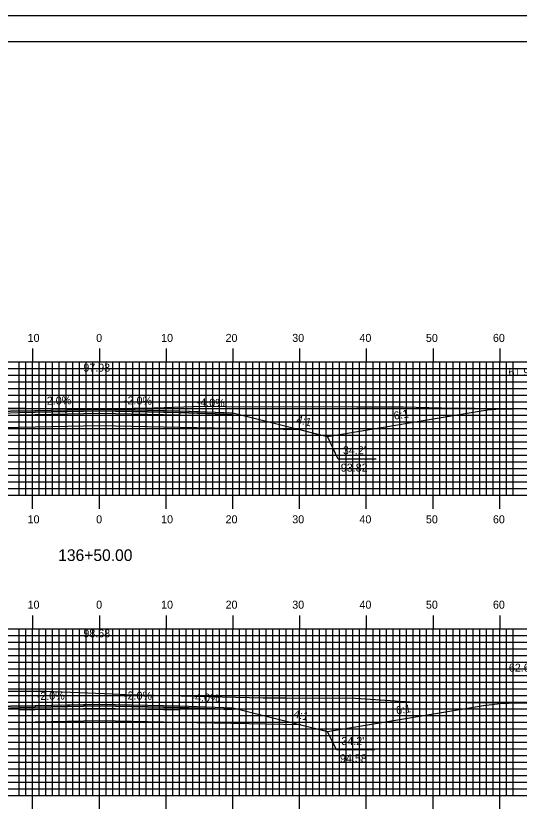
# Model space of a CAD drawing. Extents: x 1775170 to 1775514, y 442591 to 442811.
# Drawn here: x 1775323.7 to 1775399.1, y 442691.2 to 442810.5 of the extents above; entities that cross this region are included whole.
import ezdxf

# ---------------------------------------------------------------- set-up
doc = ezdxf.new("R2010")
doc.units = 0
for name, color, linetype in [('ANNOTATION', 7, 'Continuous'), ('BORDER', 7, 'Continuous'), ('D_Roadway_Centerline', 7, 'Continuous'), ('D_Roadway_Centerline_Text', 7, 'Continuous'), ('D_Roadway_Edge_Shoulder', 7, 'Continuous'), ('D_Roadway_Edge_TW', 7, 'Continuous'), ('D_Roadway_Pavement', 7, 'Continuous'), ('D_Roadway_SlopeLines', 7, 'Continuous'), ('D_Roadway_SubGrade', 7, 'Continuous'), ('D_Text_Standard', 7, 'Continuous'), ('H_V ANNOTATION', 7, 'Continuous'), ('MAJOR', 7, 'Continuous'), ('MINOR', 7, 'Continuous'), ('PLOT BOUNDARY', 7, 'Continuous'), ('S_Roadway_Centerline', 7, 'Continuous')]:
    doc.layers.add(name, color=color, linetype=linetype)

msp = doc.modelspace()

# ---------------------------------------------------------------- linework, layer by layer
at = {"layer": 'ANNOTATION'}
for points in [[(1775377.65, 442744.09), (1775371.96, 442744.09), (1775370.37, 442747.49)], [(1775377.42, 442700.49), (1775371.73, 442700.49), (1775370.37, 442703.24)]]:
    msp.add_lwpolyline(points, dxfattribs=at)
at = {"layer": 'BORDER'}
msp.add_lwpolyline([(1775186.6, 442596.67), (1775506.6, 442596.67), (1775506.6, 442806.67), (1775186.6, 442806.67)], close=True, dxfattribs=at)
at = {"layer": 'D_Roadway_Centerline'}
for points in [[(1775316.2, 442751.03), (1775324.2, 442751.35), (1775326.46, 442751.4), (1775336.2, 442751.59), (1775344.24, 442751.43), (1775348.2, 442751.35), (1775349.77, 442751.29), (1775356.2, 442751.03), (1775363.58, 442749.19), (1775366.37, 442748.49), (1775368.69, 442747.91), (1775370.37, 442747.49), (1775393.09, 442751.28), (1775394.34, 442751.46), (1775395.59, 442751.58), (1775396.58, 442751.63), (1775396.84, 442751.64), (1775398.09, 442751.65)], [(1775316.2, 442706.78), (1775324.2, 442707.1), (1775334.23, 442707.3), (1775336.2, 442707.34), (1775348.2, 442707.1), (1775352.22, 442706.94), (1775356.2, 442706.78), (1775361.8, 442705.38), (1775366.37, 442704.24), (1775369.62, 442703.43), (1775370.37, 442703.24), (1775393.77, 442707.14), (1775393.82, 442707.15), (1775395.02, 442707.32), (1775395.83, 442707.4), (1775396.27, 442707.45), (1775396.93, 442707.48), (1775397.52, 442707.52), (1775398.77, 442707.53)]]:
    msp.add_lwpolyline(points, dxfattribs=at)
at = {"layer": 'D_Roadway_Edge_Shoulder'}
for points in [[(1775324.2, 442751.35), (1775316.2, 442751.03), (1775316.2, 442750.78), (1775324.2, 442751.1)], [(1775348.2, 442751.35), (1775356.2, 442751.03), (1775356.2, 442750.78), (1775348.2, 442751.1)], [(1775324.2, 442707.1), (1775316.2, 442706.78), (1775316.2, 442706.53), (1775324.2, 442706.85)], [(1775348.2, 442707.1), (1775356.2, 442706.78), (1775356.2, 442706.53), (1775348.2, 442706.85)]]:
    msp.add_lwpolyline(points, close=True, dxfattribs=at)
at = {"layer": 'D_Roadway_Edge_TW'}
for points in [[(1775324.2, 442751.1), (1775324.2, 442751.35), (1775336.2, 442751.59), (1775348.2, 442751.35), (1775348.2, 442751.1), (1775336.2, 442751.34)], [(1775324.2, 442706.85), (1775324.2, 442707.1), (1775336.2, 442707.34), (1775348.2, 442707.1), (1775348.2, 442706.85), (1775336.2, 442707.09)]]:
    msp.add_lwpolyline(points, close=True, dxfattribs=at)
at = {"layer": 'D_Roadway_Pavement'}
for points in [[(1775324.2, 442750.69), (1775324.2, 442751.1), (1775336.2, 442751.34), (1775348.2, 442751.1), (1775348.2, 442750.69), (1775336.2, 442750.93)], [(1775324.2, 442706.44), (1775324.2, 442706.85), (1775336.2, 442707.09), (1775348.2, 442706.85), (1775348.2, 442706.44), (1775336.2, 442706.68)]]:
    msp.add_lwpolyline(points, close=True, dxfattribs=at)
at = {"layer": 'D_Roadway_SlopeLines'}
for points in [[(1775370.37, 442747.49), (1775393.09, 442751.28), (1775394.34, 442751.46), (1775395.59, 442751.58), (1775396.84, 442751.64), (1775398.09, 442751.65)], [(1775356.2, 442751.03), (1775370.37, 442747.49)], [(1775370.37, 442703.24), (1775393.77, 442707.14), (1775395.02, 442707.32), (1775396.27, 442707.45), (1775397.52, 442707.52), (1775398.77, 442707.53)], [(1775356.2, 442706.78), (1775370.37, 442703.24)]]:
    msp.add_lwpolyline(points, dxfattribs=at)
at = {"layer": 'D_Roadway_SubGrade'}
for points in [[(1775324.2, 442748.85), (1775306.02, 442748.49), (1775316.2, 442751.03), (1775316.2, 442750.78), (1775324.2, 442751.1), (1775336.2, 442751.34), (1775348.2, 442751.1), (1775356.2, 442750.78), (1775356.2, 442751.03), (1775366.37, 442748.49), (1775348.2, 442748.85), (1775336.2, 442749.09)], [(1775324.2, 442704.6), (1775306.02, 442704.24), (1775316.2, 442706.78), (1775316.2, 442706.53), (1775324.2, 442706.85), (1775336.2, 442707.09), (1775348.2, 442706.85), (1775356.2, 442706.53), (1775356.2, 442706.78), (1775366.37, 442704.24), (1775348.2, 442704.6), (1775336.2, 442704.84)]]:
    msp.add_lwpolyline(points, close=True, dxfattribs=at)
at = {"layer": 'MAJOR'}
for p, q in [((1775326.2, 442760.67), (1775326.2, 442758.67)), ((1775336.2, 442760.67), (1775336.2, 442758.67)), ((1775346.2, 442760.67), (1775346.2, 442758.67)), ((1775356.2, 442760.67), (1775356.2, 442758.67)), ((1775366.2, 442760.67), (1775366.2, 442758.67)), ((1775376.2, 442760.67), (1775376.2, 442758.67)), ((1775386.2, 442760.67), (1775386.2, 442758.67)), ((1775396.2, 442760.67), (1775396.2, 442758.67)), ((1775196.2, 442758.67), (1775476.2, 442758.67)), ((1775196.2, 442758.67), (1775476.2, 442758.67)), ((1775326.2, 442738.67), (1775326.2, 442758.67)), ((1775336.2, 442738.67), (1775336.2, 442758.67)), ((1775346.2, 442738.67), (1775346.2, 442758.67)), ((1775356.2, 442738.67), (1775356.2, 442758.67)), ((1775366.2, 442738.67), (1775366.2, 442758.67)), ((1775376.2, 442738.67), (1775376.2, 442758.67)), ((1775386.2, 442738.67), (1775386.2, 442758.67)), ((1775396.2, 442738.67), (1775396.2, 442758.67)), ((1775196.2, 442753.67), (1775476.2, 442753.67)), ((1775196.2, 442748.67), (1775476.2, 442748.67)), ((1775196.2, 442743.67), (1775476.2, 442743.67)), ((1775196.2, 442738.67), (1775476.2, 442738.67)), ((1775196.2, 442738.67), (1775476.2, 442738.67)), ((1775326.2, 442736.66), (1775326.2, 442738.67)), ((1775336.2, 442736.66), (1775336.2, 442738.67)), ((1775346.2, 442736.66), (1775346.2, 442738.67)), ((1775356.2, 442736.66), (1775356.2, 442738.67)), ((1775366.2, 442736.66), (1775366.2, 442738.67)), ((1775376.2, 442736.66), (1775376.2, 442738.67)), ((1775386.2, 442736.66), (1775386.2, 442738.67)), ((1775396.2, 442736.66), (1775396.2, 442738.67)), ((1775326.2, 442720.67), (1775326.2, 442718.67)), ((1775336.2, 442720.67), (1775336.2, 442718.67)), ((1775346.2, 442720.67), (1775346.2, 442718.67)), ((1775356.2, 442720.67), (1775356.2, 442718.67)), ((1775366.2, 442720.67), (1775366.2, 442718.67)), ((1775376.2, 442720.67), (1775376.2, 442718.67)), ((1775386.2, 442720.67), (1775386.2, 442718.67)), ((1775396.2, 442720.67), (1775396.2, 442718.67)), ((1775196.2, 442718.67), (1775476.2, 442718.67)), ((1775196.2, 442718.67), (1775476.2, 442718.67)), ((1775326.2, 442693.67), (1775326.2, 442718.67)), ((1775336.2, 442693.67), (1775336.2, 442718.67)), ((1775346.2, 442693.67), (1775346.2, 442718.67)), ((1775356.2, 442693.67), (1775356.2, 442718.67)), ((1775366.2, 442693.67), (1775366.2, 442718.67)), ((1775376.2, 442693.67), (1775376.2, 442718.67)), ((1775386.2, 442693.67), (1775386.2, 442718.67)), ((1775396.2, 442693.67), (1775396.2, 442718.67)), ((1775196.2, 442713.67), (1775476.2, 442713.67)), ((1775196.2, 442708.67), (1775476.2, 442708.67)), ((1775196.2, 442703.67), (1775476.2, 442703.67)), ((1775196.2, 442698.67), (1775476.2, 442698.67)), ((1775196.2, 442693.67), (1775476.2, 442693.67)), ((1775196.2, 442693.67), (1775476.2, 442693.67)), ((1775326.2, 442691.66), (1775326.2, 442693.67)), ((1775336.2, 442691.66), (1775336.2, 442693.67)), ((1775346.2, 442691.66), (1775346.2, 442693.67)), ((1775356.2, 442691.66), (1775356.2, 442693.67)), ((1775366.2, 442691.66), (1775366.2, 442693.67)), ((1775376.2, 442691.66), (1775376.2, 442693.67)), ((1775386.2, 442691.66), (1775386.2, 442693.67)), ((1775396.2, 442691.66), (1775396.2, 442693.67))]:
    msp.add_line(p, q, dxfattribs=at)
at = {"layer": 'MINOR'}
for p, q in [((1775324.2, 442738.67), (1775324.2, 442758.67)), ((1775325.2, 442738.67), (1775325.2, 442758.67)), ((1775327.2, 442738.67), (1775327.2, 442758.67)), ((1775328.2, 442738.67), (1775328.2, 442758.67)), ((1775329.2, 442738.67), (1775329.2, 442758.67)), ((1775330.2, 442738.67), (1775330.2, 442758.67)), ((1775331.2, 442738.67), (1775331.2, 442758.67)), ((1775332.2, 442738.67), (1775332.2, 442758.67)), ((1775333.2, 442738.67), (1775333.2, 442758.67)), ((1775334.2, 442738.67), (1775334.2, 442758.67)), ((1775335.2, 442738.67), (1775335.2, 442758.67)), ((1775337.2, 442738.67), (1775337.2, 442758.67)), ((1775338.2, 442738.67), (1775338.2, 442758.67)), ((1775339.2, 442738.67), (1775339.2, 442758.67)), ((1775340.2, 442738.67), (1775340.2, 442758.67)), ((1775341.2, 442738.67), (1775341.2, 442758.67)), ((1775342.2, 442738.67), (1775342.2, 442758.67)), ((1775343.2, 442738.67), (1775343.2, 442758.67)), ((1775344.2, 442738.67), (1775344.2, 442758.67)), ((1775345.2, 442738.67), (1775345.2, 442758.67)), ((1775347.2, 442738.67), (1775347.2, 442758.67)), ((1775348.2, 442738.67), (1775348.2, 442758.67)), ((1775349.2, 442738.67), (1775349.2, 442758.67)), ((1775350.2, 442738.67), (1775350.2, 442758.67)), ((1775351.2, 442738.67), (1775351.2, 442758.67)), ((1775352.2, 442738.67), (1775352.2, 442758.67)), ((1775353.2, 442738.67), (1775353.2, 442758.67)), ((1775354.2, 442738.67), (1775354.2, 442758.67)), ((1775355.2, 442738.67), (1775355.2, 442758.67)), ((1775357.2, 442738.67), (1775357.2, 442758.67)), ((1775358.2, 442738.67), (1775358.2, 442758.67)), ((1775359.2, 442738.67), (1775359.2, 442758.67)), ((1775360.2, 442738.67), (1775360.2, 442758.67)), ((1775361.2, 442738.67), (1775361.2, 442758.67)), ((1775362.2, 442738.67), (1775362.2, 442758.67)), ((1775363.2, 442738.67), (1775363.2, 442758.67)), ((1775364.2, 442738.67), (1775364.2, 442758.67)), ((1775365.2, 442738.67), (1775365.2, 442758.67)), ((1775367.2, 442738.67), (1775367.2, 442758.67)), ((1775368.2, 442738.67), (1775368.2, 442758.67)), ((1775369.2, 442738.67), (1775369.2, 442758.67)), ((1775370.2, 442738.67), (1775370.2, 442758.67)), ((1775371.2, 442738.67), (1775371.2, 442758.67)), ((1775372.2, 442738.67), (1775372.2, 442758.67)), ((1775373.2, 442738.67), (1775373.2, 442758.67)), ((1775374.2, 442738.67), (1775374.2, 442758.67)), ((1775375.2, 442738.67), (1775375.2, 442758.67)), ((1775377.2, 442738.67), (1775377.2, 442758.67)), ((1775378.2, 442738.67), (1775378.2, 442758.67)), ((1775379.2, 442738.67), (1775379.2, 442758.67)), ((1775380.2, 442738.67), (1775380.2, 442758.67)), ((1775381.2, 442738.67), (1775381.2, 442758.67)), ((1775382.2, 442738.67), (1775382.2, 442758.67)), ((1775383.2, 442738.67), (1775383.2, 442758.67)), ((1775384.2, 442738.67), (1775384.2, 442758.67)), ((1775385.2, 442738.67), (1775385.2, 442758.67)), ((1775387.2, 442738.67), (1775387.2, 442758.67)), ((1775388.2, 442738.67), (1775388.2, 442758.67)), ((1775389.2, 442738.67), (1775389.2, 442758.67)), ((1775390.2, 442738.67), (1775390.2, 442758.67)), ((1775391.2, 442738.67), (1775391.2, 442758.67)), ((1775392.2, 442738.67), (1775392.2, 442758.67)), ((1775393.2, 442738.67), (1775393.2, 442758.67)), ((1775394.2, 442738.67), (1775394.2, 442758.67)), ((1775395.2, 442738.67), (1775395.2, 442758.67)), ((1775397.2, 442738.67), (1775397.2, 442758.67)), ((1775398.2, 442738.67), (1775398.2, 442758.67)), ((1775196.2, 442757.67), (1775476.2, 442757.67)), ((1775196.2, 442756.67), (1775476.2, 442756.67)), ((1775196.2, 442755.67), (1775476.2, 442755.67)), ((1775196.2, 442754.67), (1775476.2, 442754.67)), ((1775196.2, 442752.67), (1775476.2, 442752.67)), ((1775196.2, 442751.67), (1775476.2, 442751.67)), ((1775196.2, 442750.67), (1775476.2, 442750.67)), ((1775196.2, 442749.67), (1775476.2, 442749.67)), ((1775196.2, 442747.67), (1775476.2, 442747.67)), ((1775196.2, 442746.67), (1775476.2, 442746.67)), ((1775196.2, 442745.67), (1775476.2, 442745.67)), ((1775196.2, 442744.67), (1775476.2, 442744.67)), ((1775196.2, 442742.67), (1775476.2, 442742.67)), ((1775196.2, 442741.67), (1775476.2, 442741.67)), ((1775196.2, 442740.67), (1775476.2, 442740.67)), ((1775196.2, 442739.67), (1775476.2, 442739.67)), ((1775324.2, 442693.67), (1775324.2, 442718.67)), ((1775325.2, 442693.67), (1775325.2, 442718.67)), ((1775327.2, 442693.67), (1775327.2, 442718.67)), ((1775328.2, 442693.67), (1775328.2, 442718.67)), ((1775329.2, 442693.67), (1775329.2, 442718.67)), ((1775330.2, 442693.67), (1775330.2, 442718.67)), ((1775331.2, 442693.67), (1775331.2, 442718.67)), ((1775332.2, 442693.67), (1775332.2, 442718.67)), ((1775333.2, 442693.67), (1775333.2, 442718.67)), ((1775334.2, 442693.67), (1775334.2, 442718.67)), ((1775335.2, 442693.67), (1775335.2, 442718.67)), ((1775337.2, 442693.67), (1775337.2, 442718.67)), ((1775338.2, 442693.67), (1775338.2, 442718.67)), ((1775339.2, 442693.67), (1775339.2, 442718.67)), ((1775340.2, 442693.67), (1775340.2, 442718.67)), ((1775341.2, 442693.67), (1775341.2, 442718.67)), ((1775342.2, 442693.67), (1775342.2, 442718.67)), ((1775343.2, 442693.67), (1775343.2, 442718.67)), ((1775344.2, 442693.67), (1775344.2, 442718.67)), ((1775345.2, 442693.67), (1775345.2, 442718.67)), ((1775347.2, 442693.67), (1775347.2, 442718.67)), ((1775348.2, 442693.67), (1775348.2, 442718.67)), ((1775349.2, 442693.67), (1775349.2, 442718.67)), ((1775350.2, 442693.67), (1775350.2, 442718.67)), ((1775351.2, 442693.67), (1775351.2, 442718.67)), ((1775352.2, 442693.67), (1775352.2, 442718.67)), ((1775353.2, 442693.67), (1775353.2, 442718.67)), ((1775354.2, 442693.67), (1775354.2, 442718.67)), ((1775355.2, 442693.67), (1775355.2, 442718.67)), ((1775357.2, 442693.67), (1775357.2, 442718.67)), ((1775358.2, 442693.67), (1775358.2, 442718.67)), ((1775359.2, 442693.67), (1775359.2, 442718.67)), ((1775360.2, 442693.67), (1775360.2, 442718.67)), ((1775361.2, 442693.67), (1775361.2, 442718.67)), ((1775362.2, 442693.67), (1775362.2, 442718.67)), ((1775363.2, 442693.67), (1775363.2, 442718.67)), ((1775364.2, 442693.67), (1775364.2, 442718.67)), ((1775365.2, 442693.67), (1775365.2, 442718.67)), ((1775367.2, 442693.67), (1775367.2, 442718.67)), ((1775368.2, 442693.67), (1775368.2, 442718.67)), ((1775369.2, 442693.67), (1775369.2, 442718.67)), ((1775370.2, 442693.67), (1775370.2, 442718.67)), ((1775371.2, 442693.67), (1775371.2, 442718.67)), ((1775372.2, 442693.67), (1775372.2, 442718.67)), ((1775373.2, 442693.67), (1775373.2, 442718.67)), ((1775374.2, 442693.67), (1775374.2, 442718.67)), ((1775375.2, 442693.67), (1775375.2, 442718.67)), ((1775377.2, 442693.67), (1775377.2, 442718.67)), ((1775378.2, 442693.67), (1775378.2, 442718.67)), ((1775379.2, 442693.67), (1775379.2, 442718.67)), ((1775380.2, 442693.67), (1775380.2, 442718.67)), ((1775381.2, 442693.67), (1775381.2, 442718.67)), ((1775382.2, 442693.67), (1775382.2, 442718.67)), ((1775383.2, 442693.67), (1775383.2, 442718.67)), ((1775384.2, 442693.67), (1775384.2, 442718.67)), ((1775385.2, 442693.67), (1775385.2, 442718.67)), ((1775387.2, 442693.67), (1775387.2, 442718.67)), ((1775388.2, 442693.67), (1775388.2, 442718.67)), ((1775389.2, 442693.67), (1775389.2, 442718.67)), ((1775390.2, 442693.67), (1775390.2, 442718.67)), ((1775391.2, 442693.67), (1775391.2, 442718.67)), ((1775392.2, 442693.67), (1775392.2, 442718.67)), ((1775393.2, 442693.67), (1775393.2, 442718.67)), ((1775394.2, 442693.67), (1775394.2, 442718.67)), ((1775395.2, 442693.67), (1775395.2, 442718.67)), ((1775397.2, 442693.67), (1775397.2, 442718.67)), ((1775398.2, 442693.67), (1775398.2, 442718.67)), ((1775196.2, 442717.67), (1775476.2, 442717.67)), ((1775196.2, 442716.67), (1775476.2, 442716.67)), ((1775196.2, 442715.67), (1775476.2, 442715.67)), ((1775196.2, 442714.67), (1775476.2, 442714.67)), ((1775196.2, 442712.67), (1775476.2, 442712.67)), ((1775196.2, 442711.67), (1775476.2, 442711.67)), ((1775196.2, 442710.67), (1775476.2, 442710.67)), ((1775196.2, 442709.67), (1775476.2, 442709.67)), ((1775196.2, 442707.67), (1775476.2, 442707.67)), ((1775196.2, 442706.67), (1775476.2, 442706.67)), ((1775196.2, 442705.67), (1775476.2, 442705.67)), ((1775196.2, 442704.67), (1775476.2, 442704.67)), ((1775196.2, 442702.67), (1775476.2, 442702.67)), ((1775196.2, 442701.67), (1775476.2, 442701.67)), ((1775196.2, 442700.67), (1775476.2, 442700.67)), ((1775196.2, 442699.67), (1775476.2, 442699.67)), ((1775196.2, 442697.67), (1775476.2, 442697.67)), ((1775196.2, 442696.67), (1775476.2, 442696.67)), ((1775196.2, 442695.67), (1775476.2, 442695.67)), ((1775196.2, 442694.67), (1775476.2, 442694.67))]:
    msp.add_line(p, q, dxfattribs=at)
at = {"layer": 'PLOT BOUNDARY'}
msp.add_lwpolyline([(1775170.41, 442590.55), (1775510.41, 442590.55), (1775510.41, 442810.55), (1775170.41, 442810.55)], close=True, dxfattribs=at)
at = {"layer": 'S_Roadway_Centerline'}
for points in [[(1775248.52, 442751.12), (1775267.46, 442751.03), (1775272.93, 442751), (1775282.9, 442751.15), (1775290.4, 442751.31), (1775297.79, 442751.39), (1775304.85, 442751.38), (1775311.93, 442751.61), (1775321.84, 442751.77), (1775328.56, 442751.66), (1775335.27, 442751.62), (1775344.39, 442751.79), (1775351.81, 442752.02), (1775358.68, 442751.94), (1775368.26, 442752), (1775374.79, 442751.93), (1775381.79, 442751.94), (1775387.46, 442751.79), (1775392.41, 442751.75), (1775403.92, 442751.56)], [(1775257.1, 442708.39), (1775268.25, 442709.02), (1775270.54, 442709.07), (1775291.68, 442709.94), (1775292.24, 442709.97), (1775292.27, 442709.97), (1775292.3, 442709.96), (1775293.03, 442709.95), (1775314.53, 442709.3), (1775316.13, 442709.31), (1775328.06, 442709.29), (1775338.2, 442708.9), (1775340.24, 442708.8), (1775360.74, 442708.31), (1775362.47, 442708.3), (1775364.22, 442708.29), (1775374.57, 442708.26), (1775382.75, 442707.71), (1775385.58, 442707.67), (1775407.68, 442707.44)]]:
    msp.add_lwpolyline(points, dxfattribs=at)

# ---------------------------------------------------------------- texts
at = {"layer": 'ANNOTATION'}
for s, rotation, p in [('-2.0%', 1.1457, (1775327.8, 442752.23)), ('-2.0%', 358.8542, (1775339.88, 442752.32)), ('-4.0%', 357.7093, (1775350.77, 442752.05)), ('6:1', 9.4632, (1775380.41, 442749.99)), ('4:1', 345.9629, (1775365.64, 442749.53)), ('-2.0%', 1.1458, (1775326.82, 442707.96)), ('-2.0%', 358.8543, (1775339.88, 442708.07)), ('-4.0%', 357.7093, (1775349.99, 442707.83)), ('4:1', 345.9618, (1775365.22, 442705.39)), ('6:1', 9.4613, (1775380.75, 442705.8))]:
    msp.add_text(s, height=1.2, rotation=rotation, dxfattribs=at).set_placement(p)
for s, p in [("34.2'", (1775372.69, 442744.82)), ('93.82', (1775372.38, 442742.22)), ("34.2'", (1775372.46, 442701.22)), ('94.58', (1775372.25, 442698.62))]:
    msp.add_text(s, height=1.2, dxfattribs=at).set_placement(p)
at = {"layer": 'D_Roadway_Centerline'}
for s, p in [('C', (1775336.19, 442751.59)), ('L', (1775336.2, 442751.59)), ('C', (1775336.19, 442707.34)), ('L', (1775336.2, 442707.34))]:
    msp.add_text(s, height=0.0146, dxfattribs=at).set_placement(p)
at = {"layer": 'D_Roadway_Centerline_Text'}
for s, p in [('97.93', (1775333.8, 442757.21)), ('98.68', (1775333.8, 442717.37))]:
    msp.add_text(s, height=1.2, dxfattribs=at).set_placement(p)
at = {"layer": 'D_Text_Standard'}
for s, p in [("61.9'", (1775397.51, 442756.56)), ("62.6'", (1775397.56, 442712.23))]:
    msp.add_text(s, height=1.2, dxfattribs=at).set_placement(p)
at = {"layer": 'H_V ANNOTATION'}
for s, height, p in [('10', 1.2, (1775325.45, 442761.67)), ('0', 1.2, (1775335.72, 442761.67)), ('10', 1.2, (1775345.45, 442761.67)), ('20', 1.2, (1775355.11, 442761.67)), ('30', 1.2, (1775365.1, 442761.67)), ('40', 1.2, (1775375.17, 442761.67)), ('50', 1.2, (1775385.13, 442761.67)), ('60', 1.2, (1775395.17, 442761.67)), ('10', 1.2, (1775325.45, 442734.47)), ('0', 1.2, (1775335.72, 442734.47)), ('10', 1.2, (1775345.45, 442734.47)), ('20', 1.2, (1775355.11, 442734.47)), ('30', 1.2, (1775365.1, 442734.47)), ('40', 1.2, (1775375.17, 442734.47)), ('50', 1.2, (1775385.13, 442734.47)), ('60', 1.2, (1775395.17, 442734.47)), ('136+50.00', 1.75, (1775330.03, 442728.82)), ('10', 1.2, (1775325.45, 442721.67)), ('0', 1.2, (1775335.72, 442721.67)), ('10', 1.2, (1775345.45, 442721.67)), ('20', 1.2, (1775355.11, 442721.67)), ('30', 1.2, (1775365.1, 442721.67)), ('40', 1.2, (1775375.17, 442721.67)), ('50', 1.2, (1775385.13, 442721.67)), ('60', 1.2, (1775395.17, 442721.67))]:
    msp.add_text(s, height=height, dxfattribs=at).set_placement(p)

doc.saveas('drawing.dxf')
